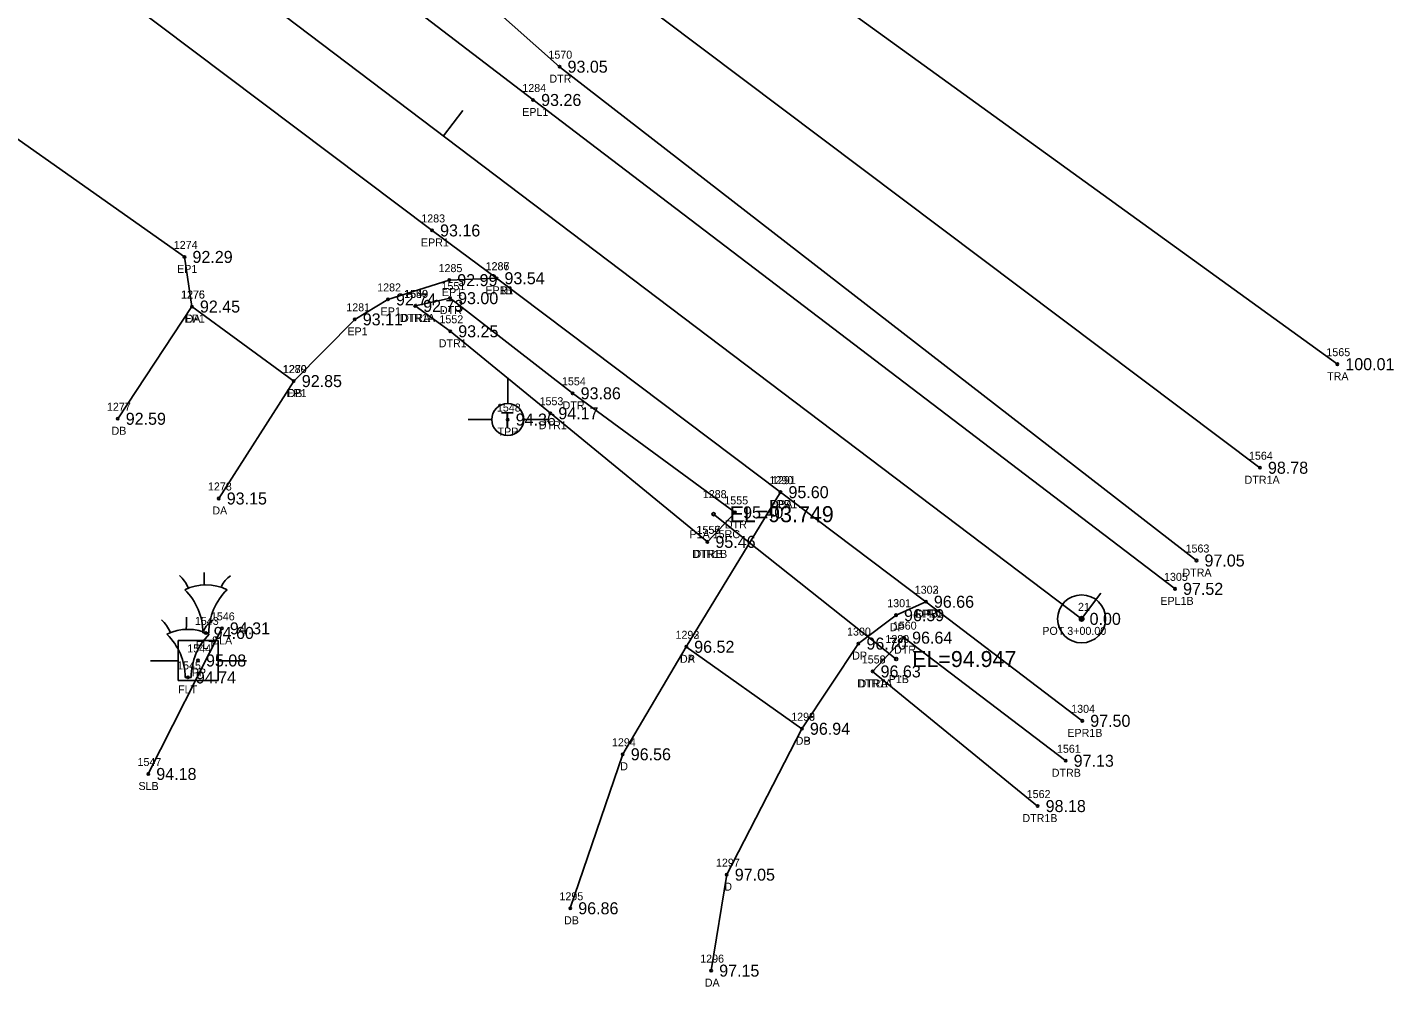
# Model space of a CAD drawing. Extents: x 2529517 to 2532038, y 935000 to 936944.
# Drawn here: x 2531867.5 to 2532038.2, y 936110.8 to 936230.7 of the extents above; entities that cross this region are included whole.
import ezdxf

# ---------------------------------------------------------------- set-up
doc = ezdxf.new("R2010")
doc.units = 0
for name, color, linetype in [('Default', 7, 'Continuous'), ('RD_EX_BldgApp', 7, 'Continuous'), ('RD_EX_BldgApp_txCode', 7, 'Continuous'), ('RD_EX_DR_Pipe', 7, 'Continuous'), ('RD_EX_DR_Pipe_txCode', 7, 'Continuous'), ('RD_EX_Driveway', 7, 'Continuous'), ('RD_EX_Driveway_txCode', 7, 'Continuous'), ('RD_EX_H2O', 7, 'Continuous'), ('RD_EX_H2O_txCode', 7, 'Continuous'), ('RD_EX_Road', 7, 'Continuous'), ('RD_EX_Road_txCode', 7, 'Continuous'), ('RD_EX_TX_BldgApp_ELEV', 7, 'Continuous'), ('RD_EX_TX_Driveway_ELEV', 7, 'Continuous'), ('RD_EX_TX_H2O_ELEV', 7, 'Continuous'), ('RD_EX_TX_Road_ELEV', 7, 'Continuous'), ('RD_EX_TX_UT_ELEV', 7, 'Continuous'), ('RD_EX_TX_VEG_ELEV', 7, 'Continuous'), ('RD_EX_UT', 7, 'Continuous'), ('RD_EX_UT_txCode', 7, 'Continuous'), ('RD_EX_VEG', 7, 'Continuous'), ('RD_EX_VEG_txCode', 7, 'Continuous'), ('RD_HC_Cl', 7, 'Continuous'), ('RD_HC_Data', 7, 'Continuous'), ('RD_HC_Data_Tic', 7, 'Continuous'), ('RD_HC_Survey_ELEV', 7, 'Continuous'), ('RD_HC_txCode', 7, 'Continuous'), ('RD_SMD_Locator', 7, 'Continuous'), ('RD_TX_Pipe_ElevEX', 7, 'Continuous')]:
    doc.layers.add(name, color=color, linetype=linetype)

msp = doc.modelspace()

# ---------------------------------------------------------------- linework, layer by layer
at = {"layer": 'Default'}
msp.add_line((2531759.99, 936337.77), (2531999.23, 936156.76), dxfattribs=at)
at = {"layer": 'RD_EX_BldgApp'}
for p, q in [((2531889.42, 936155.02), (2531890.17, 936155.02)), ((2531887.2, 936149.45), (2531887.95, 936149.45))]:
    msp.add_line(p, q, dxfattribs=at)
for centre, radius, start, end in [((2531883.11, 936158.66), 4.89, 24.3279, 46.2665), ((2531851.72, 936162.36), 37.88, 358.0671, 0.2715), ((2531894.69, 936159.41), 3.28, 123.2906, 154.4886), ((2531889.8, 936155.02), 6, 63.7794, 116.2206), ((2531881.92, 936155.02), 7.5, 0, 45.8366), ((2531897.67, 936155.02), 7.5, 134.1634, 180), ((2531880.88, 936153.1), 4.89, 24.3279, 46.2665), ((2531849.49, 936156.79), 37.88, 358.0671, 0.2715), ((2531892.46, 936153.85), 3.28, 123.2906, 154.4886), ((2531887.57, 936149.45), 6, 63.7794, 116.2206), ((2531879.7, 936149.45), 7.5, 0, 45.8366), ((2531895.45, 936149.45), 7.5, 134.1634, 180)]:
    msp.add_arc(centre, radius, start, end, dxfattribs=at)
at = {"layer": 'RD_EX_DR_Pipe'}
msp.add_line((2531953.24, 936169.84), (2531976.06, 936151.74), dxfattribs=at)
at = {"layer": 'RD_EX_Driveway'}
for p, q in [((2531888.05, 936195.78), (2531878.78, 936181.76)), ((2531891.4, 936171.8), (2531900.78, 936186.47))]:
    msp.add_line(p, q, dxfattribs=at)
for points in [[(2531961.6, 936172.59), (2531949.82, 936153.27), (2531964.28, 936143.03), (2531971.34, 936153.67), (2531976.04, 936157.22), (2531979.77, 936158.9)], [(2531949.82, 936153.27), (2531941.89, 936139.84), (2531935.33, 936120.6)], [(2531952.94, 936112.81), (2531954.89, 936124.8), (2531964.28, 936143.03)]]:
    msp.add_lwpolyline(points, dxfattribs=at)
at = {"layer": 'RD_EX_H2O'}
msp.add_line((2531973.11, 936150.19), (2531993.74, 936133.37), dxfattribs=at)
for points in [[(2532013.59, 936164.05), (2531933.99, 936225.75), (2531895.93, 936259.56), (2531897, 936261.91), (2531899.89, 936263.49), (2531899.92, 936263.44)], [(2532021.52, 936175.64), (2531941.85, 936235.58), (2531899.92, 936263.44)], [(2531915.95, 936195.86), (2531920.31, 936196.83), (2531935.63, 936184.94), (2531955.93, 936170.06), (2531952.47, 936166.38)], [(2531915.95, 936195.86), (2531920.33, 936192.69), (2531932.84, 936182.45), (2531952.47, 936166.38)], [(2531973.11, 936150.19), (2531977.05, 936154.41), (2531997.24, 936139.03)]]:
    msp.add_lwpolyline(points, dxfattribs=at)
at = {"layer": 'RD_EX_Road'}
for points in [[(2531788.67, 936375.53), (2531784.05, 936361.55), (2531786.68, 936344.28), (2531790.66, 936334.1), (2531795.41, 936327.11), (2531801.08, 936320.84), (2531849.6, 936283.17), (2531876.01, 936264.22), (2531894.71, 936249.13), (2531930.69, 936221.59), (2532010.91, 936160.51)], [(2531730.37, 936304.55), (2531747.09, 936311.1), (2531758.83, 936311.42), (2531770.03, 936309.95), (2531779.92, 936307.38), (2531789.77, 936300.82), (2531836.93, 936266.34), (2531918.06, 936205.29), (2531926.11, 936199.32), (2531961.6, 936172.59), (2531979.77, 936158.9), (2531999.31, 936144.02)], [(2531851.56, 936227.06), (2531887.12, 936201.98), (2531888.05, 936195.78), (2531900.78, 936186.47), (2531908.4, 936194.18), (2531912.55, 936196.67), (2531920.21, 936199.08), (2531926.11, 936199.32)]]:
    msp.add_lwpolyline(points, dxfattribs=at)
at = {"layer": 'RD_EX_UT'}
for p, q in [((2531927.51, 936186.73), (2531927.51, 936183.66)), ((2531922.58, 936181.67), (2531925.51, 936181.67)), ((2531929.51, 936181.67), (2531932.58, 936181.67)), ((2531891.31, 936154.07), (2531886.31, 936154.07)), ((2531886.31, 936154.07), (2531886.31, 936149.07)), ((2531891.31, 936149.07), (2531891.31, 936154.07)), ((2531882.87, 936151.5), (2531886.34, 936151.5)), ((2531891.23, 936151.5), (2531894.87, 936151.5)), ((2531886.31, 936149.07), (2531891.31, 936149.07))]:
    msp.add_line(p, q, dxfattribs=at)
msp.add_circle((2531927.51, 936181.66), 2, dxfattribs=at)
at = {"layer": 'RD_EX_VEG'}
msp.add_line((2531891.79, 936155.57), (2531882.6, 936137.38), dxfattribs=at)
msp.add_lwpolyline([(2532031.19, 936188.58), (2531930.89, 936261.1), (2531961.95, 936298.2)], dxfattribs=at)
at = {"layer": 'RD_HC_Cl'}
msp.add_line((2531759.99, 936337.77), (2531999.23, 936156.76), dxfattribs=at)
at = {"layer": 'RD_HC_Data'}
for radius in [3, 0.282]:
    msp.add_circle((2531999.23, 936156.76), radius, dxfattribs=at)
at = {"layer": 'RD_HC_Data_Tic'}
for p, q in [((2531919.48, 936217.1), (2531921.9, 936220.29)), ((2531999.23, 936156.76), (2532001.64, 936159.95))]:
    msp.add_line(p, q, dxfattribs=at)
at = {"layer": 'RD_SMD_Locator'}
for centre, radius in [((2531933.99, 936225.75), 0.15), ((2531930.69, 936221.59), 0.15), ((2531918.06, 936205.29), 0.15), ((2531887.12, 936201.98), 0.15), ((2531920.21, 936199.08), 0.15), ((2531926.11, 936199.32), 0.15), ((2531926.11, 936199.32), 0.15), ((2531888.05, 936195.78), 0.15), ((2531888.05, 936195.78), 0.15), ((2531912.55, 936196.67), 0.15), ((2531915.95, 936195.86), 0.15), ((2531915.95, 936195.86), 0.15), ((2531920.31, 936196.83), 0.15), ((2531908.4, 936194.18), 0.15), ((2531920.33, 936192.69), 0.15), ((2532031.19, 936188.58), 0.15), ((2531900.78, 936186.47), 0.15), ((2531900.78, 936186.47), 0.15), ((2531935.63, 936184.94), 0.15), ((2531932.84, 936182.45), 0.15), ((2531878.78, 936181.76), 0.15), ((2531927.51, 936181.66), 0.15), ((2532021.52, 936175.64), 0.15), ((2531891.4, 936171.8), 0.15), ((2531961.6, 936172.59), 0.15), ((2531961.6, 936172.59), 0.15), ((2531953.24, 936169.84), 0.2), ((2531955.93, 936170.06), 0.15), ((2531952.47, 936166.38), 0.15), ((2531952.47, 936166.38), 0.15), ((2532013.59, 936164.05), 0.15), ((2532010.91, 936160.51), 0.15), ((2531979.77, 936158.9), 0.15), ((2531979.77, 936158.9), 0.15), ((2531976.04, 936157.22), 0.15), ((2531999.23, 936156.76), 0.15), ((2531889.77, 936155), 0.15), ((2531891.79, 936155.57), 0.15), ((2531949.82, 936153.27), 0.15), ((2531949.82, 936153.27), 0.15), ((2531971.34, 936153.67), 0.15), ((2531977.05, 936154.41), 0.15), ((2531888.81, 936151.56), 0.15), ((2531976.06, 936151.74), 0.2), ((2531887.54, 936149.44), 0.15), ((2531973.11, 936150.19), 0.15), ((2531973.11, 936150.19), 0.15), ((2531964.28, 936143.03), 0.15), ((2531964.28, 936143.03), 0.15), ((2531999.31, 936144.02), 0.15), ((2531941.89, 936139.84), 0.15), ((2531997.24, 936139.03), 0.15), ((2531882.6, 936137.38), 0.15), ((2531993.74, 936133.37), 0.15), ((2531954.89, 936124.8), 0.15), ((2531935.33, 936120.6), 0.15), ((2531952.94, 936112.81), 0.15)]:
    msp.add_circle(centre, radius, dxfattribs=at)

# ---------------------------------------------------------------- texts
at = {"layer": 'RD_EX_BldgApp_txCode'}
for s, p in [('1543', (2531888.42, 936156)), ('FLT', (2531888.55, 936153)), ('1545', (2531886.2, 936150.44)), ('FLT', (2531886.32, 936147.44))]:
    msp.add_text(s, height=1, dxfattribs=at).set_placement(p)
at = {"layer": 'RD_EX_DR_Pipe_txCode'}
for s, p in [('1288', (2531951.89, 936171.84)), ('P1A 15RC', (2531950.23, 936166.84)), ('1289', (2531974.71, 936153.74)), ('P1B', (2531975.12, 936148.74))]:
    msp.add_text(s, height=1, dxfattribs=at).set_placement(p)
at = {"layer": 'RD_EX_Driveway_txCode'}
for s, p in [('1276', (2531886.68, 936196.78)), ('DA', (2531887.26, 936193.78)), ('1280', (2531899.4, 936187.47)), ('DB', (2531900, 936184.47)), ('1277', (2531877.43, 936182.76)), ('DB', (2531878, 936179.76)), ('1278', (2531890.05, 936172.8)), ('1291', (2531960.54, 936173.59)), ('DA', (2531890.6, 936169.8)), ('DPA', (2531960.34, 936170.59)), ('1302', (2531978.38, 936159.9)), ('1301', (2531974.94, 936158.22)), ('DPB', (2531978.51, 936156.9)), ('1292', (2531948.48, 936154.27)), ('1293', (2531948.48, 936154.27)), ('1300', (2531969.92, 936154.67)), ('DP', (2531975.26, 936155.22)), ('DA', (2531949.03, 936151.27)), ('DP', (2531949.04, 936151.27)), ('DP', (2531970.56, 936151.67)), ('1298', (2531962.94, 936144.03)), ('1299', (2531962.94, 936144.03)), ('1294', (2531940.54, 936140.84)), ('DB', (2531963.5, 936141.03)), ('DP', (2531963.5, 936141.03)), ('D', (2531941.58, 936137.84)), ('1297', (2531953.54, 936125.8)), ('1295', (2531933.98, 936121.6)), ('D', (2531954.58, 936122.8)), ('DB', (2531934.55, 936118.6)), ('1296', (2531951.57, 936113.81)), ('DA', (2531952.14, 936110.81))]:
    msp.add_text(s, height=1, dxfattribs=at).set_placement(p)
at = {"layer": 'RD_EX_H2O_txCode'}
for s, p in [('1570', (2531932.6, 936226.75)), ('DTR', (2531932.72, 936223.75)), ('1550', (2531914.56, 936196.86)), ('1549', (2531914.6, 936196.86)), ('1551', (2531919.24, 936197.83)), ('DTR', (2531919.04, 936194.83)), ('DTR1A', (2531914.03, 936193.86)), ('DTRA', (2531914.19, 936193.86)), ('1552', (2531918.98, 936193.69)), ('DTR1', (2531918.89, 936190.69)), ('1554', (2531934.29, 936185.94)), ('1553', (2531931.49, 936183.45)), ('DTR', (2531934.37, 936182.94)), ('DTR1', (2531931.4, 936180.45)), ('1564', (2532020.15, 936176.64)), ('DTR1A', (2532019.6, 936173.64)), ('1555', (2531954.58, 936171.06)), ('1556', (2531951.1, 936167.38)), ('1557', (2531951.12, 936167.38)), ('DTR', (2531954.66, 936168.06)), ('DTR1B', (2531950.56, 936164.38)), ('DTRB', (2531950.73, 936164.38)), ('1563', (2532012.22, 936165.05)), ('DTRA', (2532011.83, 936162.05)), ('1560', (2531975.64, 936155.41)), ('DTR', (2531975.79, 936152.41)), ('1558', (2531971.76, 936151.19)), ('1559', (2531971.76, 936151.19)), ('DTR1A', (2531971.19, 936148.19)), ('DTRA', (2531971.36, 936148.19)), ('1561', (2531996.15, 936140.03)), ('DTRB', (2531995.5, 936137.03)), ('1562', (2531992.37, 936134.37)), ('DTR1B', (2531991.83, 936131.37))]:
    msp.add_text(s, height=1, dxfattribs=at).set_placement(p)
at = {"layer": 'RD_EX_Road_txCode'}
for s, p in [('1284', (2531929.34, 936222.59)), ('EPL1', (2531929.32, 936219.59)), ('1283', (2531916.71, 936206.29)), ('EPR1', (2531916.67, 936203.29)), ('1274', (2531885.78, 936202.98)), ('EP1', (2531886.2, 936199.98)), ('1285', (2531918.87, 936200.08)), ('1286', (2531924.74, 936200.32)), ('1287', (2531924.76, 936200.32)), ('1275', (2531886.71, 936196.78)), ('1282', (2531911.2, 936197.67)), ('EP1', (2531919.29, 936197.08)), ('EP1B', (2531924.72, 936197.32)), ('EPR1', (2531924.72, 936197.32)), ('1281', (2531907.34, 936195.18)), ('EP1', (2531911.63, 936194.67)), ('EP1', (2531887.13, 936193.78)), ('EP1', (2531907.48, 936192.18)), ('1279', (2531899.44, 936187.47)), ('EP1', (2531899.86, 936184.47)), ('1290', (2531960.22, 936173.59)), ('EPR1', (2531960.21, 936170.59)), ('1305', (2532009.53, 936161.51)), ('1303', (2531978.38, 936159.9)), ('EPL1B', (2532009.07, 936158.51)), ('EPR1', (2531978.37, 936156.9)), ('1304', (2531997.93, 936145.02)), ('EPR1B', (2531997.45, 936142.02))]:
    msp.add_text(s, height=1, dxfattribs=at).set_placement(p)
at = {"layer": 'RD_EX_TX_BldgApp_ELEV'}
for s, p in [('94.60', (2531890.77, 936154.25)), ('94.74', (2531888.54, 936148.69))]:
    msp.add_text(s, height=1.5, dxfattribs=at).set_placement(p)
at = {"layer": 'RD_EX_TX_Driveway_ELEV'}
for s, p in [('92.45', (2531889.05, 936195.03)), ('92.85', (2531901.78, 936185.72)), ('92.59', (2531879.78, 936181.01)), ('93.15', (2531892.4, 936171.05)), ('95.60', (2531962.6, 936171.84)), ('96.66', (2531980.77, 936158.15)), ('96.59', (2531977.04, 936156.47)), ('96.52', (2531950.82, 936152.52)), ('96.52', (2531950.82, 936152.52)), ('96.70', (2531972.34, 936152.92)), ('96.94', (2531965.28, 936142.28)), ('96.94', (2531965.28, 936142.28)), ('96.56', (2531942.89, 936139.09)), ('97.05', (2531955.89, 936124.05)), ('96.86', (2531936.33, 936119.85)), ('97.15', (2531953.94, 936112.06))]:
    msp.add_text(s, height=1.5, dxfattribs=at).set_placement(p)
at = {"layer": 'RD_EX_TX_H2O_ELEV'}
for s, p in [('93.05', (2531934.99, 936225)), ('93.00', (2531921.31, 936196.08)), ('92.73', (2531916.95, 936195.11)), ('92.73', (2531916.95, 936195.11)), ('93.25', (2531921.33, 936191.94)), ('93.86', (2531936.63, 936184.19)), ('94.17', (2531933.84, 936181.7)), ('98.78', (2532022.52, 936174.89)), ('95.40', (2531956.93, 936169.31)), ('95.46', (2531953.47, 936165.63)), ('95.46', (2531953.47, 936165.63)), ('97.05', (2532014.59, 936163.3)), ('96.64', (2531978.05, 936153.66)), ('96.63', (2531974.11, 936149.44)), ('96.63', (2531974.11, 936149.44)), ('97.13', (2531998.24, 936138.28)), ('98.18', (2531994.74, 936132.62))]:
    msp.add_text(s, height=1.5, dxfattribs=at).set_placement(p)
at = {"layer": 'RD_EX_TX_Road_ELEV'}
for s, p in [('93.26', (2531931.69, 936220.84)), ('93.16', (2531919.06, 936204.54)), ('92.29', (2531888.12, 936201.23)), ('92.99', (2531921.21, 936198.33)), ('93.54', (2531927.11, 936198.57)), ('93.54', (2531927.11, 936198.57)), ('92.74', (2531913.55, 936195.92)), ('92.45', (2531889.05, 936195.03)), ('93.11', (2531909.4, 936193.43)), ('92.85', (2531901.78, 936185.72)), ('95.60', (2531962.6, 936171.84)), ('97.52', (2532011.91, 936159.76)), ('96.66', (2531980.77, 936158.15)), ('97.50', (2532000.31, 936143.27))]:
    msp.add_text(s, height=1.5, dxfattribs=at).set_placement(p)
at = {"layer": 'RD_EX_TX_UT_ELEV'}
msp.add_text('94.36', height=1.5, dxfattribs=at).set_placement((2531928.51, 936180.91))
at = {"layer": 'RD_EX_TX_VEG_ELEV'}
for s, p in [('100.01', (2532032.19, 936187.83)), ('94.31', (2531892.79, 936154.82)), ('94.18', (2531883.6, 936136.63))]:
    msp.add_text(s, height=1.5, dxfattribs=at).set_placement(p)
at = {"layer": 'RD_EX_UT'}
msp.add_text('T', height=2, dxfattribs=at).set_placement((2531926.66, 936180.61))
at = {"layer": 'RD_EX_UT_txCode'}
for s, p in [('1548', (2531926.16, 936182.66)), ('TPP', (2531926.24, 936179.66)), ('1544', (2531887.47, 936152.56)), ('PP', (2531888.03, 936149.56))]:
    msp.add_text(s, height=1, dxfattribs=at).set_placement(p)
at = {"layer": 'RD_EX_VEG_txCode'}
for s, p in [('1565', (2532029.82, 936189.58)), ('TRA', (2532029.91, 936186.58)), ('1546', (2531890.42, 936156.57)), ('SLA', (2531890.55, 936153.57)), ('1547', (2531881.25, 936138.38)), ('SLB', (2531881.37, 936135.38))]:
    msp.add_text(s, height=1, dxfattribs=at).set_placement(p)
at = {"layer": 'RD_HC_Survey_ELEV'}
for s, p in [('0.00', (2532000.23, 936156.01)), ('95.08', (2531889.81, 936150.81))]:
    msp.add_text(s, height=1.5, dxfattribs=at).set_placement(p)
at = {"layer": 'RD_HC_txCode'}
for s, p in [('21', (2531998.78, 936157.76)), ('POT 3+00.00', (2531994.32, 936154.76))]:
    msp.add_text(s, height=1, dxfattribs=at).set_placement(p)
at = {"layer": 'RD_TX_Pipe_ElevEX'}
for s, p in [('EL=93.749', (2531955.24, 936168.84)), ('EL=94.947', (2531978.06, 936150.74))]:
    msp.add_text(s, height=2, dxfattribs=at).set_placement(p)

doc.saveas('drawing.dxf')
